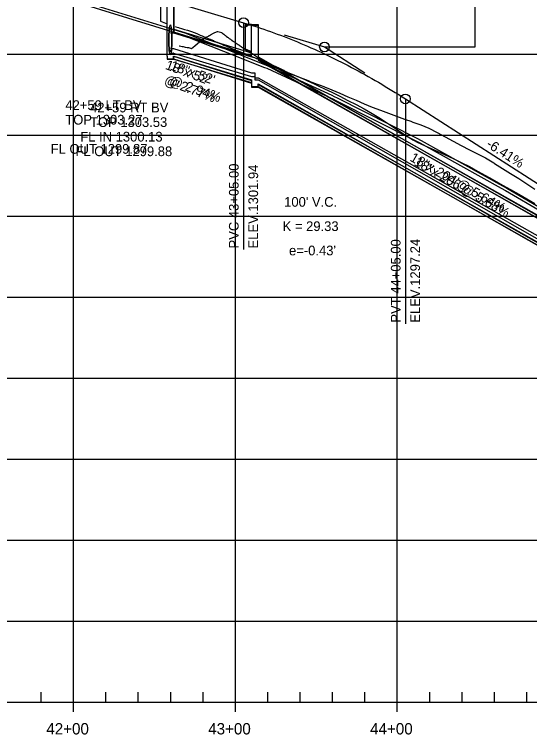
# Model space of a CAD drawing. Extents: x 670877 to 686811, y 705985 to 708501.
# Drawn here: x 685636.5 to 685954.7, y 707018.3 to 707462.9 of the extents above; entities that cross this region are included whole.
import ezdxf

# ---------------------------------------------------------------- set-up
doc = ezdxf.new("R2010")
doc.units = 0
for name, color, linetype in [('30', 7, 'Continuous'), ('37', 7, 'Continuous'), ('DRAINAGE_HGL LEFT', 7, 'Continuous'), ('DRAINAGE_HGL RIGHT', 7, 'Continuous'), ('Profile Drainage Annot Left', 7, 'Continuous'), ('Profile Drainage Annot Right', 7, 'Continuous'), ('R_Drainage Extensions_LEFT', 7, 'Continuous'), ('R_Drainage Extensions_RIGHT', 7, 'Continuous'), ('R_Drainage LEFT', 7, 'Continuous'), ('R_Drainage RIGHT', 7, 'Continuous'), ('R_Exist Surface', 7, 'Continuous'), ('R_Profile Work Left', 7, 'Continuous'), ('R_Profile Work Right', 7, 'Continuous'), ('R_Vert Alg', 7, 'Continuous'), ('R_Vert Alg Annot', 7, 'Continuous')]:
    doc.layers.add(name, color=color, linetype=linetype)

msp = doc.modelspace()

# ---------------------------------------------------------------- linework, layer by layer
at = {"layer": '37'}
for p, q in [((685673.03, 707038.43), (685673.03, 707688.43)), ((685773.03, 707038.43), (685773.03, 707688.43)), ((685873.03, 707038.43), (685873.03, 707688.43)), ((684473.03, 707438.43), (686573.03, 707438.43)), ((684473.03, 707388.43), (686573.03, 707388.43)), ((684473.03, 707338.43), (686573.03, 707338.43)), ((684473.03, 707288.43), (686573.03, 707288.43)), ((684473.03, 707238.43), (686573.03, 707238.43)), ((684473.03, 707188.43), (686573.03, 707188.43)), ((684473.03, 707138.43), (686573.03, 707138.43)), ((684473.03, 707088.43), (686573.03, 707088.43)), ((685653.03, 707038.43), (685653.03, 707044.43)), ((685693.03, 707038.43), (685693.03, 707044.43)), ((685713.03, 707038.43), (685713.03, 707044.43)), ((685733.03, 707038.43), (685733.03, 707044.43)), ((685753.03, 707038.43), (685753.03, 707044.43)), ((685793.03, 707038.43), (685793.03, 707044.43)), ((685813.03, 707038.43), (685813.03, 707044.43)), ((685833.03, 707038.43), (685833.03, 707044.43)), ((685853.03, 707038.43), (685853.03, 707044.43)), ((685893.03, 707038.43), (685893.03, 707044.43)), ((685913.03, 707038.43), (685913.03, 707044.43)), ((685933.03, 707038.43), (685933.03, 707044.43)), ((685953.03, 707038.43), (685953.03, 707044.43)), ((684473.03, 707038.43), (686573.03, 707038.43)), ((685673.03, 707032.43), (685673.03, 707038.43)), ((685773.03, 707032.43), (685773.03, 707038.43)), ((685873.03, 707032.43), (685873.03, 707038.43))]:
    msp.add_line(p, q, dxfattribs=at)
at = {"layer": 'DRAINAGE_HGL LEFT'}
for points in [[(685673.48, 707472.79), (685740.24, 707452.02), (685741.7, 707451.49), (685766.35, 707441.84), (685791.6, 707431.79), (685793.04, 707431.24), (685832.48, 707412.99), (685833.97, 707412.28), (685835.79, 707411.38), (685885.14, 707386.44), (685887.67, 707385.1), (685938.06, 707357.07), (685940.74, 707355.58), (685987.13, 707328.55), (686033.17, 707300.67), (686033.27, 707300.6), (686086.87, 707272.08), (686122.78, 707260.43), (686186.53, 707247.11), (686186.61, 707247.1), (686193.03, 707246.6), (686234.36, 707243.27), (686235.19, 707243.3), (686283.18, 707244.26)], [(685732.9, 707439.08), (685734.9, 707439.08), (685734.9, 707439.08), (685734.7, 707439.08), (685782.98, 707424.58), (685785.03, 707424.58), (685785.03, 707422.45), (685787.06, 707422.45), (685993.14, 707305.35), (685995.14, 707305.35), (685995.14, 707303.57), (685997.14, 707303.57), (686121.03, 707243.68), (686123.03, 707243.68)]]:
    msp.add_lwpolyline(points, dxfattribs=at)
at = {"layer": 'DRAINAGE_HGL RIGHT'}
msp.add_lwpolyline([(685732.83, 707441.79), (685734.83, 707441.79), (685734.83, 707441.79), (685734.83, 707441.79), (685783.01, 707426.79), (685785.03, 707426.79), (685785.03, 707423.69), (685787.06, 707423.69), (685991.16, 707308.49), (685993.16, 707308.49), (685993.16, 707306.41), (685995.16, 707306.41), (686121.03, 707249.44), (686123.03, 707249.44)], dxfattribs=at)
at = {"layer": 'R_Drainage Extensions_LEFT'}
msp.add_lwpolyline([(685782.99, 707456.63), (685778.99, 707456.63), (685778.99, 707441.63), (685782.99, 707439.96), (685782.99, 707456.63)], dxfattribs=at)
at = {"layer": 'R_Drainage Extensions_RIGHT'}
for points in [[(685730.82, 707473.73), (685726.82, 707473.73), (685726.82, 707458.73), (685730.82, 707457.06), (685730.82, 707473.73)], [(685783, 707456.23), (685779, 707456.23), (685779, 707441.23), (685783, 707439.56), (685783, 707456.23)]]:
    msp.add_lwpolyline(points, dxfattribs=at)
at = {"layer": 'R_Drainage LEFT'}
for points in [[(685730.9, 707437.13), (685730.9, 707471.13)], [(685734.9, 707471.13), (685734.9, 707452.07)], [(685782.99, 707437.63), (685782.99, 707456.63)], [(685782.99, 707456.63), (685787.07, 707456.63)], [(685787.07, 707456.63), (685787.07, 707435.13)], [(685734.9, 707453.74), (685782.99, 707439.29)], [(685734.9, 707452.07), (685782.99, 707437.63)], [(685730.9, 707437.13), (685730.9, 707435.4)], [(685730.9, 707435.4), (685734.9, 707435.4)], [(685734.9, 707435.4), (685734.9, 707437.07)], [(685734.9, 707437.07), (685782.99, 707422.63)], [(685734.9, 707435.4), (685782.99, 707420.96)], [(685787.07, 707436.79), (685993.14, 707319.7)], [(685787.07, 707435.13), (685993.14, 707318.03)], [(685782.99, 707422.63), (685782.99, 707418.46)], [(685782.99, 707418.46), (685787.07, 707418.46)], [(685787.07, 707418.46), (685787.07, 707420.13)], [(685787.07, 707420.13), (685993.14, 707303.03)], [(685787.07, 707418.46), (685993.14, 707301.36)]]:
    msp.add_lwpolyline(points, dxfattribs=at)
at = {"layer": 'R_Drainage RIGHT'}
for points in [[(685730.82, 707437.23), (685730.82, 707473.73)], [(685734.83, 707473.73), (685734.83, 707452.23)], [(685734.83, 707452.23), (685783, 707437.23)], [(685783, 707437.23), (685783, 707456.23)], [(685783, 707456.23), (685787.05, 707456.23)], [(685787.05, 707456.23), (685787.05, 707434.73)], [(685732.83, 707451.65), (685734.83, 707451.65), (685734.83, 707451.65), (685734.83, 707451.65), (685783.01, 707436.65)], [(685730.82, 707437.23), (685730.82, 707435.56)], [(685730.82, 707435.56), (685734.83, 707435.56)], [(685734.83, 707435.56), (685734.83, 707437.23)], [(685734.83, 707437.23), (685783, 707422.23)], [(685734.83, 707435.56), (685783, 707420.56)], [(685787.05, 707436.4), (685991.16, 707321.2)], [(685787.05, 707434.73), (685991.16, 707319.53)], [(685783, 707422.23), (685783, 707418.07)], [(685783, 707418.07), (685787.05, 707418.07)], [(685787.05, 707418.07), (685787.05, 707419.73)], [(685787.05, 707419.73), (685991.16, 707304.53)], [(685787.05, 707418.07), (685991.16, 707302.86)]]:
    msp.add_lwpolyline(points, dxfattribs=at)
for major_axis in [(0, 9.17), (0, 7.5)]:
    msp.add_ellipse((685732.83, 707447.23), major_axis=major_axis, ratio=0.1, dxfattribs=at)
at = {"layer": 'R_Exist Surface'}
msp.add_lwpolyline([(685673.04, 707471.18), (685739.71, 707450.44), (685741.12, 707449.93), (685765.74, 707440.28), (685790.99, 707430.24), (685792.38, 707429.7), (685831.77, 707411.47), (685833.24, 707410.78), (685835.04, 707409.88), (685884.37, 707384.95), (685886.88, 707383.63), (685937.25, 707355.61), (685939.91, 707354.13), (685986.28, 707327.12)], dxfattribs=at)
at = {"layer": 'R_Profile Work Left'}
msp.add_lwpolyline([(685738.28, 707443.54), (685738.28, 707443.54), (685738.3, 707443.53), (685738.53, 707443.49), (685740.16, 707443.17), (685740.33, 707443.13), (685740.76, 707443.05), (685742.03, 707442.79), (685742.14, 707442.77), (685743.27, 707442.54), (685743.91, 707442.42), (685743.97, 707442.41), (685745.83, 707441.92), (685747.97, 707443.63), (685751.13, 707446.18), (685752.33, 707447.17), (685753.26, 707447.78), (685754.45, 707448.46), (685754.56, 707448.52), (685755.45, 707449.03), (685756.32, 707449.54), (685756.79, 707449.81), (685756.93, 707449.9), (685757.64, 707450.31), (685759.42, 707451.37), (685759.84, 707451.58), (685761.27, 707452.11), (685761.97, 707452.37), (685762.11, 707452.42), (685764.56, 707451.67), (685764.71, 707451.56), (685765.15, 707451.21), (685765.8, 707450.72), (685766.26, 707450.36), (685766.45, 707450.22), (685766.79, 707449.96), (685767.38, 707449.52), (685768.19, 707448.91), (685768.49, 707448.68), (685768.74, 707448.5), (685769.23, 707448.14), (685769.61, 707447.86), (685769.64, 707447.84), (685769.91, 707447.64), (685770.69, 707447.08), (685770.73, 707447.05), (685770.91, 707446.92), (685771.63, 707446.4), (685771.86, 707446.24), (685772.19, 707446.01), (685772.6, 707445.73), (685772.62, 707445.71), (685772.99, 707445.46), (685773.35, 707445.21), (685773.47, 707445.13), (685774.13, 707444.68), (685774.55, 707444.4), (685774.76, 707444.26), (685775.07, 707444.05), (685775.27, 707443.92), (685775.93, 707443.47), (685776.06, 707443.39), (685776.41, 707443.16), (685776.49, 707443.11), (685776.78, 707442.92), (685777.36, 707442.54), (685777.56, 707442.41), (685778.42, 707441.85), (685778.5, 707441.8), (685778.67, 707441.69), (685778.72, 707441.66), (685779.25, 707441.32), (685779.87, 707440.93), (685779.99, 707440.85), (685780.22, 707440.71), (685780.36, 707440.62), (685781.04, 707440.2), (685781.32, 707440.02), (685781.96, 707439.64), (685782.21, 707439.48), (685782.32, 707439.41), (685782.58, 707439.25), (685782.67, 707439.2), (685782.9, 707439.06), (685783.38, 707438.77), (685783.7, 707438.58), (685784.02, 707438.39), (685784.29, 707438.23), (685784.57, 707438.06), (685785.4, 707437.45), (685785.47, 707437.39), (685785.77, 707437.15), (685785.96, 707437), (685786.3, 707436.72), (685786.8, 707436.33), (685786.89, 707436.26), (685786.98, 707436.18), (685787.34, 707435.91), (685787.83, 707435.53), (685788.51, 707435.02), (685788.67, 707434.89), (685789.58, 707434.21), (685789.98, 707433.91), (685790.26, 707433.7), (685791.2, 707433.01), (685791.81, 707432.71), (685792, 707432.61), (685793.7, 707431.81), (685793.73, 707431.79), (685794.02, 707431.66), (685794.18, 707431.58), (685795.46, 707430.99), (685796.19, 707430.67), (685796.22, 707430.66), (685797.2, 707430.22), (685798.36, 707429.72), (685798.42, 707429.69), (685798.68, 707429.58), (685798.93, 707429.48), (685798.97, 707429.46), (685800.62, 707428.77), (685800.66, 707428.75), (685801.18, 707428.54), (685802.4, 707428.06), (685802.55, 707428), (685802.91, 707427.87), (685803.94, 707427.48), (685806.94, 707426.35), (685807.55, 707426.12), (685809.95, 707425.21), (685812.55, 707424.22), (685812.97, 707424.06), (685815.98, 707422.69), (685817.55, 707421.97), (685819, 707421.29), (685822.02, 707419.88), (685822.55, 707419.63), (685825.04, 707418.46), (685827.55, 707417.27), (685828.06, 707417.03), (685832.55, 707414.88), (685837.55, 707412.39), (685842.55, 707409.82), (685847.55, 707407.22), (685852.55, 707404.59), (685857.55, 707401.8), (685862.55, 707398.58), (685867.55, 707395.33), (685872.55, 707392.06), (685877.55, 707388.78), (685878.03, 707388.46), (685881.29, 707386.31), (685882.55, 707385.48), (685885.66, 707383.93), (685887.55, 707383.06), (685892.55, 707380.77), (685897.55, 707378.48), (685902.55, 707376.18), (685907.55, 707373.89), (685912.55, 707371.6), (685917.55, 707369.01), (685922.55, 707366.22), (685927.55, 707363.43), (685931.57, 707361.19), (685932.55, 707360.64), (685933.03, 707360.38), (685938.03, 707357.58), (685943.03, 707354.74), (685948.03, 707351.89), (685953.03, 707349.04), (685958.03, 707346.19)], dxfattribs=at)
at = {"layer": 'R_Profile Work Right'}
msp.add_lwpolyline([(685736.03, 707455.39), (685736.03, 707455.39), (685736.05, 707455.38), (685736.23, 707455.32), (685737.77, 707454.85), (685737.94, 707454.8), (685738.37, 707454.67), (685739.63, 707454.28), (685739.75, 707454.25), (685740.87, 707453.9), (685741.51, 707453.7), (685741.57, 707453.68), (685743.41, 707453.12), (685745.84, 707452.37), (685749.23, 707451.08), (685750.4, 707450.58), (685751.28, 707450.21), (685752.4, 707449.73), (685752.5, 707449.69), (685753.33, 707449.33), (685754.16, 707448.98), (685754.6, 707448.8), (685754.73, 707448.74), (685755.4, 707448.45), (685757.07, 707447.74), (685757.47, 707447.58), (685758.78, 707447.02), (685759.42, 707446.75), (685759.55, 707446.69), (685761.64, 707445.81), (685761.78, 707445.75), (685762.18, 707445.58), (685762.95, 707445.26), (685763.51, 707445.02), (685763.74, 707444.93), (685764.15, 707444.76), (685764.86, 707444.46), (685765.84, 707444.04), (685766.22, 707443.88), (685766.52, 707443.75), (685767.12, 707443.5), (685767.59, 707443.3), (685767.62, 707443.28), (685767.96, 707443.14), (685768.91, 707442.74), (685768.97, 707442.71), (685769.19, 707442.62), (685770.08, 707442.24), (685770.36, 707442.12), (685770.77, 707441.95), (685771.28, 707441.73), (685771.31, 707441.72), (685771.77, 707441.53), (685772.21, 707441.35), (685772.36, 707441.29), (685773.18, 707440.96), (685773.71, 707440.75), (685773.96, 707440.64), (685774.34, 707440.49), (685774.6, 707440.38), (685775.43, 707440.05), (685775.58, 707439.98), (685776.03, 707439.8), (685776.12, 707439.76), (685776.49, 707439.61), (685777.21, 707439.32), (685777.46, 707439.22), (685778.54, 707438.78), (685778.64, 707438.74), (685778.85, 707438.65), (685778.91, 707438.63), (685779.58, 707438.35), (685780.36, 707438.04), (685780.5, 707437.98), (685780.79, 707437.86), (685780.97, 707437.79), (685781.81, 707437.45), (685782.17, 707437.3), (685782.96, 707436.98), (685783.27, 707436.85), (685783.41, 707436.8), (685783.74, 707436.66), (685783.84, 707436.62), (685784.14, 707436.5), (685784.74, 707436.26), (685785.13, 707436.1), (685785.53, 707435.94), (685785.86, 707435.8), (685786.21, 707435.67), (685787.22, 707435.25), (685787.31, 707435.22), (685787.68, 707435.07), (685787.91, 707434.98), (685788.33, 707434.81), (685788.93, 707434.57), (685789.04, 707434.52), (685789.16, 707434.48), (685789.5, 707434.34), (685789.98, 707434.14), (685790.65, 707433.88), (685790.81, 707433.81), (685791.7, 707433.45), (685792.09, 707433.29), (685792.37, 707433.18), (685793.3, 707432.81), (685793.91, 707432.55), (685794.1, 707432.46), (685795.8, 707431.71), (685795.84, 707431.69), (685796.12, 707431.56), (685796.29, 707431.49), (685797.58, 707430.92), (685798.31, 707430.59), (685798.34, 707430.58), (685799.33, 707430.14), (685800.5, 707429.58), (685800.56, 707429.55), (685800.83, 707429.42), (685801.08, 707429.3), (685801.12, 707429.28), (685802.8, 707428.46), (685802.84, 707428.44), (685803.36, 707428.18), (685804.6, 707427.58), (685804.73, 707427.52), (685805.03, 707427.37), (685805.91, 707426.95), (685808.56, 707425.82), (685809.12, 707425.6), (685811.34, 707424.7), (685813.73, 707423.73), (685814.12, 707423.58), (685816.9, 707422.47), (685818.35, 707421.9), (685819.69, 707421.38), (685822.48, 707420.29), (685822.96, 707420.1), (685825.27, 707419.21), (685827.59, 707418.33), (685828.06, 707418.15), (685832.55, 707416.45), (685837.55, 707414.29), (685842.55, 707412.12), (685847.55, 707409.95), (685852.55, 707407.76), (685857.55, 707405.7), (685862.55, 707403.81), (685867.55, 707401.91), (685872.55, 707400.06), (685877.55, 707398.28), (685878.03, 707398.1), (685881.29, 707396.94), (685882.55, 707396.49), (685885.66, 707395.37), (685887.55, 707394.69), (685892.55, 707392.63), (685897.55, 707389.98), (685902.55, 707387.34), (685907.55, 707384.7), (685912.55, 707382.06), (685917.55, 707379.41), (685922.55, 707376.89), (685927.55, 707374.38), (685931.57, 707371.91), (685932.55, 707371.29), (685933.03, 707370.99), (685938.03, 707367.87), (685943.03, 707364.75), (685948.03, 707361.62), (685953.03, 707358.42), (685958.03, 707355.11)], dxfattribs=at)
at = {"layer": 'R_Vert Alg'}
for p, q in [((685722.55, 707474.43), (685778.03, 707457.81)), ((685803.03, 707450.32), (685828.03, 707442.83)), ((685828.03, 707442.83), (685853.03, 707426.81)), ((685828.03, 707442.83), (685921.03, 707442.83)), ((685878.03, 707410.79), (686003.03, 707330.69))]:
    msp.add_line(p, q, dxfattribs=at)
msp.add_lwpolyline([(685778.03, 707457.81), (685780.11, 707457.18), (685782.2, 707456.53), (685784.28, 707455.87), (685786.36, 707455.19), (685788.45, 707454.5), (685790.53, 707453.8), (685792.61, 707453.08), (685794.7, 707452.34), (685796.78, 707451.59), (685798.86, 707450.83), (685800.95, 707450.05), (685803.03, 707449.25), (685805.11, 707448.44), (685807.2, 707447.62), (685809.28, 707446.78), (685811.36, 707445.93), (685813.45, 707445.06), (685815.53, 707444.17), (685817.61, 707443.28), (685819.7, 707442.36), (685821.78, 707441.44), (685823.86, 707440.49), (685825.95, 707439.54), (685830.11, 707437.58), (685832.2, 707436.58), (685834.28, 707435.56), (685836.36, 707434.53), (685838.45, 707433.48), (685840.53, 707432.42), (685842.61, 707431.34), (685844.7, 707430.25), (685846.78, 707429.15), (685848.86, 707428.03), (685850.95, 707426.89), (685853.03, 707425.74), (685855.11, 707424.58), (685857.2, 707423.4), (685859.28, 707422.2), (685861.36, 707421), (685863.45, 707419.77), (685865.53, 707418.53), (685867.61, 707417.28), (685869.7, 707416.01), (685871.78, 707414.73), (685873.86, 707413.43), (685875.95, 707412.12), (685878.03, 707410.79)], dxfattribs=at)
for centre in [(685778.03, 707457.81), (685828.03, 707442.83), (685878.03, 707410.79)]:
    msp.add_circle(centre, 3, dxfattribs=at)
at = {"layer": 'R_Vert Alg Annot'}
for p, q in [((685921.03, 707442.83), (685921.03, 707549.53)), ((685778.03, 707457.81), (685778.03, 707317.7)), ((685878.03, 707410.79), (685878.03, 707271.96))]:
    msp.add_line(p, q, dxfattribs=at)

# ---------------------------------------------------------------- texts
at = {"layer": '30'}
for s, p in [('42+00', (685656.22, 707018.43)), ('43+00', (685756.22, 707018.43)), ('44+00', (685856.22, 707018.43))]:
    msp.add_text(s, height=7, dxfattribs=at).set_placement(p)
at = {"layer": 'Profile Drainage Annot Left'}
for s, rotation, p in [('18"x 52\'', 339.554, (685729.31, 707429.36)), ('@ 2.77%', 339.554, (685728.55, 707420.04)), ('18"x 206\'@ 5.68%', 330.2055, (685882.99, 707370.11))]:
    msp.add_text(s, height=6, rotation=rotation, dxfattribs=at).set_placement(p)
for s, p in [('42+59 LT BV', (685667.97, 707403.92)), ('TOP 1303.27', (685667.93, 707394.92)), ('FL OUT 1299.87', (685658.93, 707376.92))]:
    msp.add_text(s, height=6, dxfattribs=at).set_placement(p)
at = {"layer": 'Profile Drainage Annot Right'}
for s, rotation, p in [('18"x 52\'', 340.4581, (685732.3, 707428.99)), ('@ 2.94%', 340.4581, (685731.69, 707419.66)), ('18"x 204\'@ 5.64%', 330.4518, (685880.33, 707372.83))]:
    msp.add_text(s, height=6, rotation=rotation, dxfattribs=at).set_placement(p)
for s, p in [('42+59 RT BV', (685683.22, 707402.44)), ('TOP 1303.53', (685683.19, 707393.44)), ('FL IN 1300.13', (685677.19, 707384.44)), ('FL OUT 1299.88', (685674.21, 707375.44))]:
    msp.add_text(s, height=6, dxfattribs=at).set_placement(p)
at = {"layer": 'R_Vert Alg Annot'}
for s, rotation, p in [('-6.41%', 327.3489, (685927.46, 707381.49)), ('PVC 43+05.00', 90, (685775.03, 707318.45)), ('ELEV.1301.94', 90, (685787.03, 707318.45)), ('PVT 44+05.00', 90, (685875.03, 707272.65)), ('ELEV.1297.24', 90, (685887.03, 707272.65))]:
    msp.add_text(s, height=6, rotation=rotation, dxfattribs=at).set_placement(p)
for s, p in [("100' V.C.", (685803.13, 707344.19)), ('K = 29.33', (685802.18, 707329.19)), ("e=-0.43'", (685806.13, 707314.19))]:
    msp.add_text(s, height=6, dxfattribs=at).set_placement(p)

doc.saveas('drawing.dxf')
